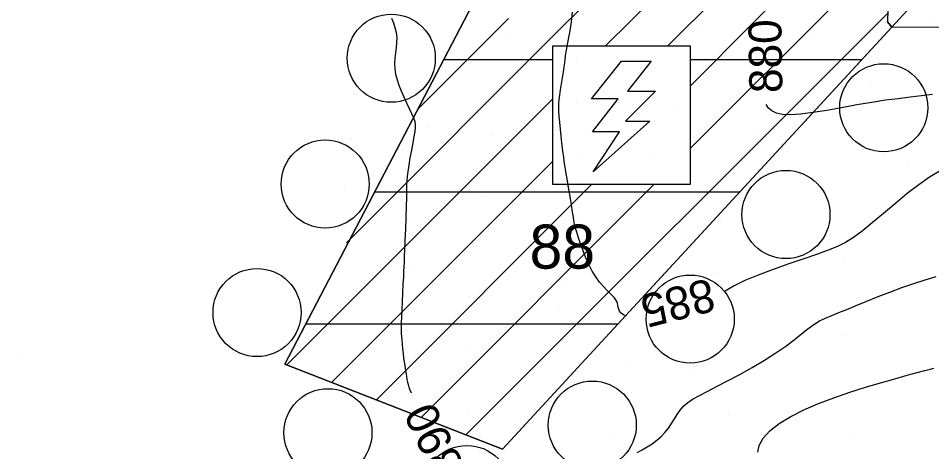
# Model space of a CAD drawing. Extents: x 400243 to 403697, y 4403637 to 4408083.
# Drawn here: x 402500 to 402707.4, y 4405978.9 to 4406077.2 of the extents above; entities that cross this region are included whole.
import ezdxf

# ---------------------------------------------------------------- set-up
doc = ezdxf.new("R2010")
doc.units = 0
for name, color, linetype in [('ADAKENARI', 7, 'Continuous'), ('HH_DiS', 7, 'Continuous'), ('HH_IC', 7, 'Continuous'), ('PL_GES', 7, 'Continuous'), ('SNR_MULKIYET', 7, 'Continuous'), ('SNR_ONAMA', 7, 'Continuous'), ('SNR_SEMBOL', 7, 'Continuous'), ('TR_GES', 7, 'Continuous')]:
    doc.layers.add(name, color=color, linetype=linetype)

msp = doc.modelspace()

# ---------------------------------------------------------------- linework, layer by layer
at = {"layer": 'ADAKENARI'}
for p, q in [((402560.49, 4405998.76), (402635.88, 4406143.05)), ((402698.51, 4406122.19), (402697.33, 4406076.45)), ((402698.29, 4406075.22), (402697.33, 4406076.45)), ((402698.29, 4406075.22), (402714.51, 4406075.31)), ((402698.29, 4406075.22), (402609.95, 4405979.43)), ((402609.95, 4405979.43), (402560.49, 4405998.76))]:
    msp.add_line(p, q, dxfattribs=at)
at = {"layer": 'HH_DiS'}
msp.add_line((402500, 4406000), (402500, 4406000), dxfattribs=at)
at = {"layer": 'HH_IC'}
for p, q in [((402681.13, 4406076.27), (402681.13, 4406076.27)), ((402707.2, 4406076.95), (402707.2, 4406076.95)), ((402594.52, 4406073.87), (402594.52, 4406073.87)), ((402611.01, 4406073.27), (402611.01, 4406073.27)), ((402654.11, 4406074.86), (402654.11, 4406074.86)), ((402679.54, 4406073.41), (402679.54, 4406073.41)), ((402576.07, 4406071.98), (402576.07, 4406071.98)), ((402626.73, 4406068.28), (402626.73, 4406068.28)), ((402593.76, 4406061.66), (402593.76, 4406061.66)), ((402610.01, 4406061.86), (402610.01, 4406061.86)), ((402672.87, 4406062.62), (402672.87, 4406062.62)), ((402693.37, 4406061.58), (402693.37, 4406061.58)), ((402576.26, 4406059.98), (402576.26, 4406059.98)), ((402626.82, 4406057.79), (402626.82, 4406057.79)), ((402648.79, 4406057.01), (402648.79, 4406057.01)), ((402691.74, 4406057.36), (402691.74, 4406057.36)), ((402593.14, 4406052.45), (402593.14, 4406052.45)), ((402607.52, 4406050.62), (402607.52, 4406050.62)), ((402666.82, 4406051.11), (402666.82, 4406051.11)), ((402575.37, 4406049.68), (402575.37, 4406049.68)), ((402627.04, 4406045.47), (402627.04, 4406045.47)), ((402643.87, 4406045.85), (402643.87, 4406045.85)), ((402702.12, 4406044.44), (402702.12, 4406044.44)), ((402662.31, 4406042.24), (402662.31, 4406042.24)), ((402574.07, 4406038.08), (402574.07, 4406038.08)), ((402590.43, 4406039.3), (402590.43, 4406039.3)), ((402642.42, 4406038.09), (402642.42, 4406038.09)), ((402605.22, 4406037.08), (402605.22, 4406037.08)), ((402659.43, 4406031.96), (402659.43, 4406031.96)), ((402627.55, 4406030.79), (402627.55, 4406030.79)), ((402603.28, 4406026.18), (402603.28, 4406026.18)), ((402683.64, 4406026.33), (402683.64, 4406026.33)), ((402642.52, 4406023.96), (402642.52, 4406023.96)), ((402687.47, 4406022.1), (402687.47, 4406022.1)), ((402571.43, 4406020.77), (402571.43, 4406020.77)), ((402589.14, 4406020.36), (402589.14, 4406020.36)), ((402658.01, 4406019.54), (402658.01, 4406019.54)), ((402623.53, 4406016.64), (402623.53, 4406016.64)), ((402602.54, 4406014.12), (402602.54, 4406014.12)), ((402622.74, 4406012.25), (402622.74, 4406012.25)), ((402641.47, 4406012.91), (402641.47, 4406012.91)), ((402569.28, 4406005.84), (402569.28, 4406005.84)), ((402588.07, 4406006.41), (402588.07, 4406006.41)), ((402687.76, 4406005.26), (402687.76, 4406005.26)), ((402623.7, 4406003.78), (402623.7, 4406003.78)), ((402601.83, 4406002.47), (402601.83, 4406002.47)), ((402638.88, 4405998.79), (402638.88, 4405998.79)), ((402653.57, 4405996.52), (402653.57, 4405996.52)), ((402569.36, 4405995.34), (402569.36, 4405995.34)), ((402586.14, 4405994.29), (402586.14, 4405994.29)), ((402621.32, 4405994.15), (402621.32, 4405994.15)), ((402639.25, 4405992.37), (402639.25, 4405992.37)), ((402602.16, 4405988.31), (402602.16, 4405988.31)), ((402661.33, 4405987.12), (402661.33, 4405987.12)), ((402620.06, 4405983.56), (402620.06, 4405983.56)), ((402635.14, 4405982.24), (402635.14, 4405982.24)), ((402689.64, 4405982.44), (402689.64, 4405982.44))]:
    msp.add_line(p, q, dxfattribs=at)
for points in [[(402638.05, 4406009.62), (402637.38, 4406009.94), (402636.85, 4406010.31), (402636.51, 4406010.74), (402636.31, 4406011.19), (402636.21, 4406011.66), (402636.14, 4406012.12), (402636.06, 4406012.55), (402635.91, 4406012.95), (402635.67, 4406013.35), (402635.34, 4406013.77), (402634.9, 4406014.25), (402634.33, 4406014.83), (402633.63, 4406015.54), (402632.84, 4406016.38), (402631.99, 4406017.38), (402631.13, 4406018.53), (402630.3, 4406019.85), (402629.52, 4406021.33), (402628.83, 4406022.88), (402628.22, 4406024.43), (402627.7, 4406025.88), (402627.27, 4406027.15), (402626.94, 4406028.16), (402626.71, 4406028.93), (402626.54, 4406029.52), (402626.42, 4406029.95), (402626.34, 4406030.28), (402626.28, 4406030.55), (402626.22, 4406030.88), (402626.14, 4406031.36), (402626.02, 4406032.12), (402625.84, 4406033.26), (402625.58, 4406034.86), (402625.27, 4406036.77), (402624.94, 4406038.8), (402624.62, 4406040.76), (402624.34, 4406042.47), (402624.12, 4406043.79), (402623.96, 4406044.82), (402623.82, 4406045.7), (402623.7, 4406046.6), (402623.57, 4406047.66), (402623.42, 4406048.99), (402623.25, 4406050.51), (402623.08, 4406052.1), (402622.93, 4406053.64), (402622.81, 4406055.01), (402622.74, 4406056.12), (402622.72, 4406057.05), (402622.74, 4406057.9), (402622.82, 4406058.77), (402622.95, 4406059.78), (402623.13, 4406060.99), (402623.34, 4406062.33), (402623.56, 4406063.72), (402623.77, 4406065.03), (402623.94, 4406066.18), (402624.07, 4406067.1), (402624.17, 4406067.88), (402624.27, 4406068.68), (402624.42, 4406069.62), (402624.64, 4406070.85), (402624.95, 4406072.45), (402625.3, 4406074.36), (402625.61, 4406076.44), (402625.82, 4406078.58)], [(402584.75, 4406077.28), (402585.16, 4406076.2), (402585.52, 4406075.12), (402585.78, 4406074.02), (402585.91, 4406072.9), (402585.89, 4406071.74), (402585.77, 4406070.56), (402585.61, 4406069.35), (402585.47, 4406068.14), (402585.41, 4406066.93), (402585.47, 4406065.72), (402585.67, 4406064.51), (402585.99, 4406063.29), (402586.41, 4406062.03), (402586.93, 4406060.74), (402587.52, 4406059.4), (402588.15, 4406058.05), (402588.76, 4406056.77), (402589.31, 4406055.6), (402589.73, 4406054.6), (402590.01, 4406053.79), (402590.13, 4406053.09), (402590.13, 4406052.37), (402590.02, 4406051.52), (402589.82, 4406050.42), (402589.55, 4406048.98), (402589.25, 4406047.33), (402588.93, 4406045.59), (402588.65, 4406043.93), (402588.42, 4406042.48), (402588.28, 4406041.35), (402588.2, 4406040.39), (402588.17, 4406039.41), (402588.15, 4406038.22), (402588.12, 4406036.61), (402588.06, 4406034.47), (402587.98, 4406031.96), (402587.88, 4406029.34), (402587.78, 4406026.83), (402587.7, 4406024.7), (402587.63, 4406023.09), (402587.58, 4406021.88), (402587.53, 4406020.86), (402587.48, 4406019.81), (402587.42, 4406018.53), (402587.34, 4406016.86), (402587.24, 4406014.94), (402587.15, 4406012.93), (402587.06, 4406011.03), (402586.99, 4406009.42), (402586.95, 4406008.23), (402586.92, 4406007.39), (402586.92, 4406006.78), (402586.93, 4406006.26), (402586.96, 4406005.7), (402587.01, 4406005.01), (402587.07, 4406004.19), (402587.14, 4406003.25), (402587.24, 4406002.23), (402587.36, 4406001.16), (402587.49, 4406000.04), (402587.65, 4405998.93), (402587.81, 4405997.87), (402587.97, 4405996.88), (402588.11, 4405996.01), (402588.25, 4405995.29), (402588.38, 4405994.67), (402588.52, 4405994.1), (402588.7, 4405993.53), (402588.92, 4405992.92), (402589.2, 4405992.2)], [(402707.52, 4406059.96), (402705.07, 4406059.62), (402702.5, 4406059.31), (402699.79, 4406058.98), (402696.88, 4406058.61), (402693.75, 4406058.15), (402690.39, 4406057.57), (402686.93, 4406056.94), (402683.54, 4406056.33), (402680.37, 4406055.81), (402677.59, 4406055.46), (402675.32, 4406055.33), (402673.53, 4406055.43), (402672.15, 4406055.73), (402671.11, 4406056.21), (402670.34, 4406056.85), (402669.78, 4406057.64)], [(402709.1, 4406042.49), (402706.84, 4406041.14), (402704.43, 4406039.46), (402701.83, 4406037.45), (402699.12, 4406035.22), (402696.44, 4406032.94), (402693.89, 4406030.79), (402691.59, 4406028.92), (402689.61, 4406027.46), (402687.8, 4406026.34), (402685.96, 4406025.42), (402683.9, 4406024.58), (402681.41, 4406023.69), (402678.36, 4406022.66), (402674.95, 4406021.49), (402671.41, 4406020.25), (402668, 4406018.97), (402664.98, 4406017.7), (402662.52, 4406016.48), (402660.51, 4406015.34)], [(402640.54, 4405978.71), (402641.67, 4405979.31), (402642.81, 4405979.96), (402643.91, 4405980.68), (402644.96, 4405981.47), (402645.93, 4405982.33), (402646.82, 4405983.25), (402647.62, 4405984.23), (402648.31, 4405985.26), (402648.95, 4405986.31), (402649.59, 4405987.35), (402650.28, 4405988.34), (402651.08, 4405989.25), (402652.04, 4405990.07), (402653.22, 4405990.84), (402654.66, 4405991.65), (402656.41, 4405992.56), (402658.53, 4405993.64), (402661.03, 4405994.94), (402663.79, 4405996.43), (402666.64, 4405998.02), (402669.43, 4405999.67), (402672, 4406001.29), (402674.23, 4406002.85), (402676.13, 4406004.29), (402677.79, 4406005.6), (402679.26, 4406006.76), (402680.61, 4406007.74), (402681.91, 4406008.54), (402683.24, 4406009.2), (402684.66, 4406009.81), (402686.25, 4406010.44), (402688.09, 4406011.17), (402690.23, 4406012.04), (402692.63, 4406013.02), (402695.2, 4406014.06), (402697.89, 4406015.11), (402700.6, 4406016.12), (402703.29, 4406017.03), (402705.9, 4406017.86), (402708.37, 4406018.6)], [(402667.87, 4405978.81), (402668.17, 4405980.32), (402669.11, 4405981.94), (402670.66, 4405983.61), (402672.76, 4405985.26), (402675.36, 4405986.85), (402678.36, 4405988.36), (402681.66, 4405989.78), (402685.16, 4405991.11), (402688.75, 4405992.36), (402692.33, 4405993.5), (402695.78, 4405994.54), (402698.97, 4405995.45), (402701.78, 4405996.22), (402704.09, 4405996.84), (402705.81, 4405997.3), (402707.03, 4405997.63), (402707.87, 4405997.86)]]:
    msp.add_lwpolyline(points, dxfattribs=at)
at = {"layer": 'PL_GES'}
msp.add_lwpolyline([(402649.95, 4406132.25), (402678.87, 4406136.48), (402678.5, 4406122.19), (402698.51, 4406122.19), (402697.33, 4406076.45), (402698.29, 4406075.22), (402609.95, 4405979.43), (402560.49, 4405998.76), (402635.88, 4406143.05)], close=True, dxfattribs=at)
at = {"layer": 'SNR_MULKIYET'}
for p, q in [((402635.88, 4406143.05), (402560.49, 4405998.76)), ((402609.95, 4405979.43), (402707.56, 4406085.27)), ((402560.49, 4405998.76), (402609.95, 4405979.43))]:
    msp.add_line(p, q, dxfattribs=at)
at = {"layer": 'SNR_ONAMA'}
for centre in [(402584.68, 4406068.17), (402696.49, 4406056.92), (402569.67, 4406039.62), (402674.28, 4406032.7), (402554.21, 4406010.46), (402652.54, 4406008.97), (402630.31, 4405984.91), (402570.3, 4405983.18), (402601.84, 4405970.28)]:
    msp.add_circle(centre, 10, dxfattribs=at)
at = {"layer": 'SNR_SEMBOL'}
for points in [[(402621.27, 4406070.88), (402621.27, 4406039.57), (402652.58, 4406039.57), (402652.58, 4406070.88)], [(402643.71, 4406067.51), (402638.32, 4406060.7), (402644.67, 4406060.7), (402637.83, 4406053.9), (402643.37, 4406053.9), (402630.54, 4406042.4), (402636.52, 4406051.49), (402630.33, 4406051.49), (402636.21, 4406058.92), (402630.17, 4406058.92), (402636.98, 4406067.51)]]:
    msp.add_lwpolyline(points, close=True, dxfattribs=at)
at = {"layer": 'TR_GES'}
for p, q in [((402625.31, 4406077.06), (402678.72, 4406130.47)), ((402639.26, 4406076.87), (402684.58, 4406122.19)), ((402653.21, 4406076.67), (402698.5, 4406121.97)), ((402667.15, 4406076.48), (402698.13, 4406107.45)), ((402652.58, 4406047.77), (402697.75, 4406092.94)), ((402601.64, 4405982.68), (402697.38, 4406078.42)), ((402574.51, 4406026.26), (402625.25, 4406077)), ((402590.72, 4406056.61), (402611.3, 4406077.19)), ((402633.27, 4406070.88), (402639.2, 4406076.81)), ((402647.41, 4406070.88), (402653.15, 4406076.61)), ((402652.58, 4406061.91), (402667.09, 4406076.42)), ((402596.6, 4406067.88), (402621.27, 4406067.88)), ((402652.58, 4406067.88), (402691.52, 4406067.88)), ((402560.97, 4405998.58), (402621.27, 4406058.88)), ((402571.14, 4405994.6), (402621.27, 4406044.74)), ((402581.3, 4405990.63), (402630.24, 4406039.57)), ((402591.47, 4405986.65), (402644.38, 4406039.57)), ((402580.93, 4406037.88), (402663.85, 4406037.88)), ((402565.26, 4406007.88), (402636.19, 4406007.88))]:
    msp.add_line(p, q, dxfattribs=at)

# ---------------------------------------------------------------- texts
at = {"layer": 'HH_IC'}
for s, rotation, p in [('880', 90.8797, (402673.49, 4406060.31)), ('885', 194.2851, (402656.98, 4406018.31)), ('890', 115.7576, (402601.37, 4405975.59))]:
    msp.add_text(s, height=7.5, rotation=rotation, dxfattribs=at).set_placement(p)
at = {"layer": 'SNR_MULKIYET'}
msp.add_text('88', height=10, dxfattribs=at).set_placement((402616.07, 4406020.41))

doc.saveas('drawing.dxf')
